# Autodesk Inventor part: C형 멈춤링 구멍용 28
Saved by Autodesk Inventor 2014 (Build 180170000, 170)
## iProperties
Created: 2026-08
Part Number: C형 멈춤링 구멍용 28
Material: 강철, 연강
Document SubType Name: Modeling
Designer: dg
Density: 7.86 g/cm^3
Appearance: 강철
Mass: 1.79919 g
Surface Area: 5.88022 cm^2
Volume: 0.228905 cm^3
Author: jhkim
Description: 리테이닝 링(C형)
Creation Date: 2026-07-31
Sending System: Autodesk Inventor 2027
Preprocessor: ST-DEVELOPER v20.1
Author: dg
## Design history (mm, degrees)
node "C형 멈춤링 구멍용 281"
body "Solid1"
node "기준1"
